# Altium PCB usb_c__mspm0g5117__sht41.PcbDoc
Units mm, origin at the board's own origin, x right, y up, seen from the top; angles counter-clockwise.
Board outline 92 x 60 mm, 2 copper layers (Top, Bottom), stack 0 mm thick; 35 components, 31 nets, 176 pads, 58 vias.
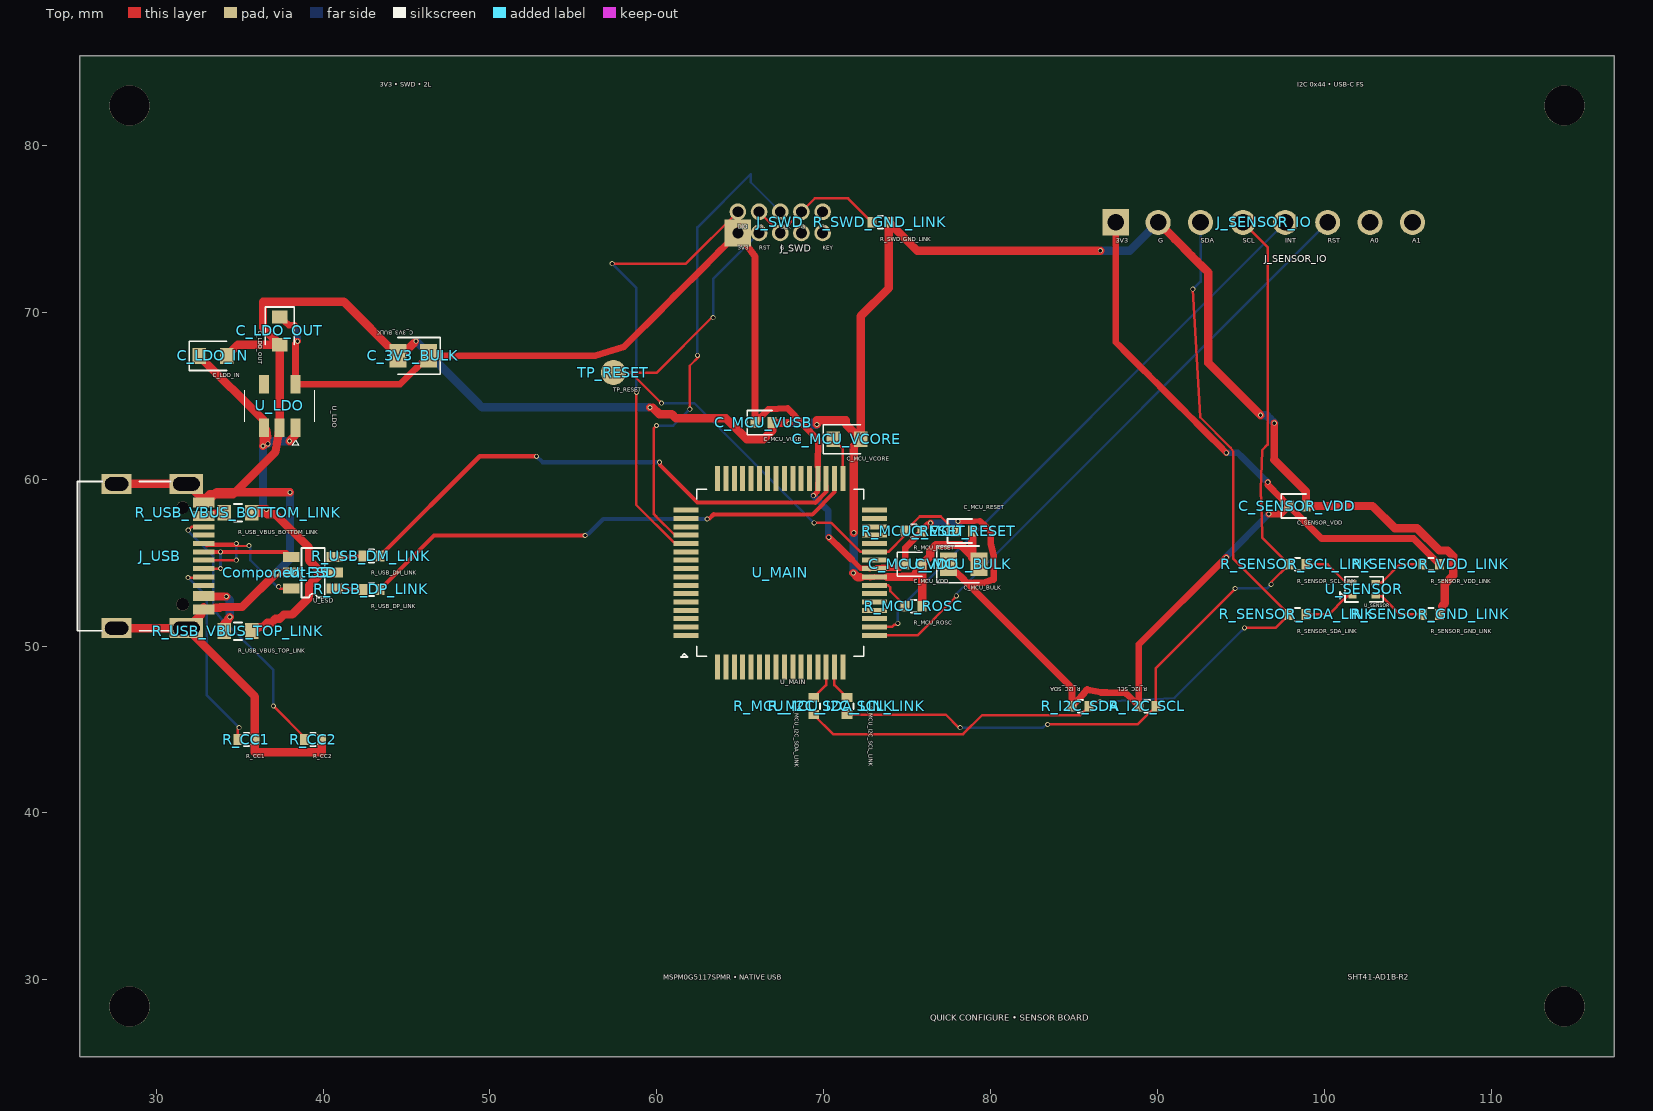
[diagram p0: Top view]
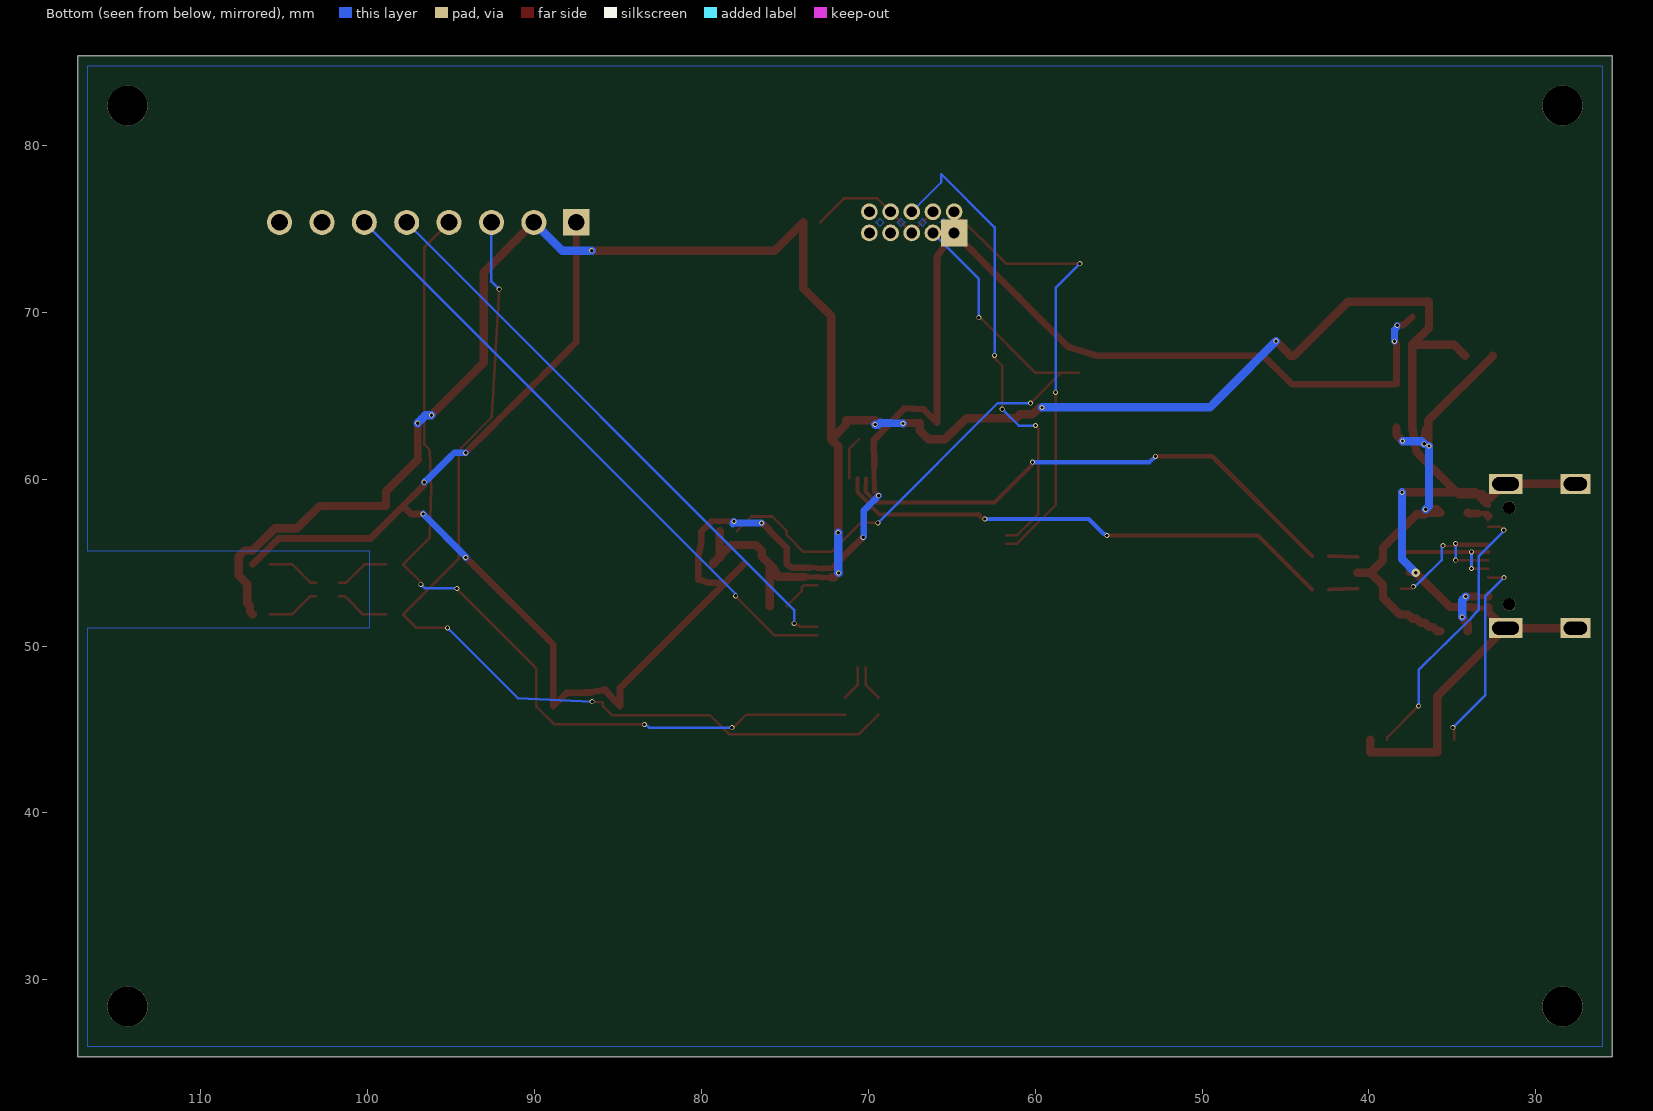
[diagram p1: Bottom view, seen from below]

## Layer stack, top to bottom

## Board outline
25.4,85.4 117.4,85.4 117.4,25.4 25.4,25.4

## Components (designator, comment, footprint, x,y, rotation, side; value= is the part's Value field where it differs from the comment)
C_3V3_BULK "" TSCIRCUIT-2.8500x1.4000mm 45.4,67.4 r180 top
C_LDO_IN "" TSCIRCUIT-2.4500x0.9500mm 33.4,67.4 r0 top
C_LDO_OUT "" TSCIRCUIT-0.9500x2.4500mm 37.4,68.9 r270 top
C_MCU_BULK "" TSCIRCUIT-2.8500x1.4000mm 78.4,54.9 r0 top
C_MCU_RESET "" TSCIRCUIT-1.5600x0.6400mm 78.4,56.9 r0 top
C_MCU_VCORE "" TSCIRCUIT-2.4500x0.9500mm 71.4,62.4 r0 top
C_MCU_VDD "" TSCIRCUIT-1.5600x0.6400mm 75.4,54.9 r0 top
C_MCU_VUSB "" TSCIRCUIT-1.5600x0.6400mm 66.4,63.4 r0 top
C_SENSOR_VDD "" TSCIRCUIT-1.5600x0.6400mm 98.4,58.4 r0 top
Component-35 "" TSCIRCUIT-0.5000x0.5000mm 37.2,54.4 r0 top
J_SENSOR_IO "" TSCIRCUIT-19.2800x1.5000mm 96.4,75.4 r0 top
J_SWD "" TSCIRCUIT-6.0800x2.2700mm 67.4,75.4 r0 top
J_USB "" TSCIRCUIT-6.7732x9.8502mm 30.113,55.4 r90 top
R_CC1 "" TSCIRCUIT-1.5600x0.6400mm 35.4,44.4 r0 top
R_CC2 "" TSCIRCUIT-1.5600x0.6400mm 39.4,44.4 r0 top
R_I2C_SCL "" TSCIRCUIT-1.5600x0.6400mm 89.4,46.4 r180 top
R_I2C_SDA "" TSCIRCUIT-1.5600x0.6400mm 85.4,46.4 r180 top
R_MCU_I2C_SCL_LINK "" TSCIRCUIT-0.6400x1.5600mm 71.4,46.4 r270 top
R_MCU_I2C_SDA_LINK "" TSCIRCUIT-0.6400x1.5600mm 69.4,46.4 r270 top
R_MCU_RESET "" TSCIRCUIT-1.5600x0.6400mm 75.4,56.9 r0 top
R_MCU_ROSC "" TSCIRCUIT-1.5600x0.6400mm 75.4,52.4 r0 top
R_SENSOR_GND_LINK "" TSCIRCUIT-1.5600x0.6400mm 106.4,51.9 r0 top
R_SENSOR_SCL_LINK "" TSCIRCUIT-1.5600x0.6400mm 98.4,54.9 r0 top
R_SENSOR_SDA_LINK "" TSCIRCUIT-1.5600x0.6400mm 98.4,51.9 r0 top
R_SENSOR_VDD_LINK "" TSCIRCUIT-1.5600x0.6400mm 106.4,54.9 r0 top
R_SWD_GND_LINK "" TSCIRCUIT-1.5600x0.6400mm 73.4,75.4 r0 top
R_USB_DM_LINK "" TSCIRCUIT-1.5600x0.6400mm 42.9,55.4 r0 top
R_USB_DP_LINK "" TSCIRCUIT-1.5600x0.6400mm 42.9,53.4 r0 top
R_USB_VBUS_BOTTOM_LINK "" TSCIRCUIT-2.4500x0.9500mm 34.9,58 r0 top
R_USB_VBUS_TOP_LINK "" TSCIRCUIT-2.4500x0.9500mm 34.9,50.9 r0 top
TP_RESET "" TSCIRCUIT-1.5000x1.5000mm 57.4,66.4 r0 top
U_ESD "" TSCIRCUIT-3.6000x2.5000mm 39.4,54.4 r0 top
U_LDO "" TSCIRCUIT-2.5000x3.7000mm 37.4,64.4 r270 top
U_MAIN "" TSCIRCUIT-12.8000x12.8000mm 67.4,54.4 r0 top
U_SENSOR "" TSCIRCUIT-1.9000x1.1001mm 102.4,53.4 r0 top

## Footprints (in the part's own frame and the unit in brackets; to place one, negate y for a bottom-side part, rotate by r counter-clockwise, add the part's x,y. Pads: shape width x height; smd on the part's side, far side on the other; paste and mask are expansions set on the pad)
TSCIRCUIT-0.5000x0.5000mm [mm]
TSCIRCUIT-0.6400x1.5600mm [mm]
  rect 0.54x0.64 smd: 1(-0.51,0) 2(0.51,0)
  silkscreen extent -0.15,-0.38 0.15,0.38
TSCIRCUIT-0.9500x2.4500mm [mm]
  rect 0.8x0.95 smd: 1(-0.825,0) 2(0.825,0)
  silkscreen extent -1.43,-0.87 0.82,0.88
TSCIRCUIT-1.5000x1.5000mm [mm]
  round 1.5 smd: 1(0,0)
TSCIRCUIT-1.5600x0.6400mm [mm]
  rect 0.54x0.64 smd: 1(-0.51,0) 2(0.51,0)
  silkscreen extent -0.98,-0.72 0.51,0.72
TSCIRCUIT-1.9000x1.1001mm [mm]
  rect 0.5x0.3 smd: 1(-0.7,-0.4) 2(-0.7,0.4) 3(0.7,0.4) 4(0.7,-0.4)
  silkscreen extent -1.45,-0.75 1.15,0.75
TSCIRCUIT-2.4500x0.9500mm [mm]
  rect 0.8x0.95 smd: 1(-0.825,0) 2(0.825,0)
  silkscreen extent -1.42,-0.87 0.82,0.87
TSCIRCUIT-2.5000x3.7000mm [mm]
  rect 1.1x0.6 smd: 1(1.3,0.95) 2(1.3,0) 3(1.3,-0.95) 4(-1.3,-0.95) 5(-1.3,0.95)
  silkscreen extent -0.95,-2.1 2.35,2.1
TSCIRCUIT-2.8500x1.4000mm [mm]
  rect 1.025x1.4 smd: 1(-0.913,0) 2(0.913,0)
  silkscreen extent -1.63,-1.1 0.91,1.1
TSCIRCUIT-3.6000x2.5000mm [mm]
  rect 1x0.6 smd: 1(-1.3,-0.95) 2(-1.3,0) 3(-1.3,0.95) 4(1.3,0.95) 5(1.3,0) 6(1.3,-0.95)
  silkscreen extent -0.7,-1.49 0.7,1.49
TSCIRCUIT-6.0800x2.2700mm [mm]
  rect 1.6x1.6 hole 0.65: 1(-2.54,-0.635)
  round 1 hole 0.65: 2(-2.54,0.635) 3(-1.27,0.635) 4(0,0.635) 5(1.27,0.635) 6(2.54,0.635) 7(2.54,-0.635) 8(1.27,-0.635) 9(0,-0.635) 10(-1.27,-0.635)
TSCIRCUIT-6.7732x9.8502mm [mm]
  rect 0.3x1.3 smd: 1(-3.35,-2.737) 2(-3.05,-2.737) 3(-2.55,-2.737) 4(-2.25,-2.737) 5(-1.75,-2.737) 6(-1.25,-2.737) 7(-0.75,-2.737) 8(-0.25,-2.737) 9(0.25,-2.737) 10(0.75,-2.737) 11(1.25,-2.737) 12(1.75,-2.737) 13(2.55,-2.737) 14(2.25,-2.737) 15(3.35,-2.737) 16(3.05,-2.737)
  rect 1.2x2 hole 0.8 slot 1.6 at 90 deg: 17(-4.325,-1.693) 18(4.325,-1.693)
  rect 1.2x1.8 hole 0.8 slot 1.4 at 90 deg: 19(4.325,2.487) 20(-4.325,2.487)
  round 0.75 hole 0.75 unplated: NPTH-1(-2.9,-1.468) NPTH-2(2.9,-1.468)
  silkscreen extent -4.47,-0.75 4.47,4.83
TSCIRCUIT-12.8000x12.8000mm [mm]
  rect 1.5x0.3 smd: 1(-5.65,-3.75) 2(-5.65,-3.25) 3(-5.65,-2.75) 4(-5.65,-2.25) 5(-5.65,-1.75) 6(-5.65,-1.25) 7(-5.65,-0.75) 8(-5.65,-0.25) 9(-5.65,0.25) 10(-5.65,0.75) 11(-5.65,1.25) 12(-5.65,1.75) 13(-5.65,2.25) 14(-5.65,2.75) 15(-5.65,3.25) 16(-5.65,3.75) 33(5.65,3.75) 34(5.65,3.25) 35(5.65,2.75) 36(5.65,2.25) 37(5.65,1.75) 38(5.65,1.25) 39(5.65,0.75) 40(5.65,0.25) 41(5.65,-0.25) 42(5.65,-0.75) 43(5.65,-1.25) 44(5.65,-1.75) 45(5.65,-2.25) 46(5.65,-2.75) 47(5.65,-3.25) 48(5.65,-3.75)
  rect 0.3x1.5 smd: 17(-3.75,5.65) 18(-3.25,5.65) 19(-2.75,5.65) 20(-2.25,5.65) 21(-1.75,5.65) 22(-1.25,5.65) 23(-0.75,5.65) 24(-0.25,5.65) 25(0.25,5.65) 26(0.75,5.65) 27(1.25,5.65) 28(1.75,5.65) 29(2.25,5.65) 30(2.75,5.65) 31(3.25,5.65) 32(3.75,5.65) 49(3.75,-5.65) 50(3.25,-5.65) 51(2.75,-5.65) 52(2.25,-5.65) 53(1.75,-5.65) 54(1.25,-5.65) 55(0.75,-5.65) 56(0.25,-5.65) 57(-0.25,-5.65) 58(-0.75,-5.65) 59(-1.25,-5.65) 60(-1.75,-5.65) 61(-2.25,-5.65) 62(-2.75,-5.65) 63(-3.25,-5.65) 64(-3.75,-5.65)
  silkscreen extent -5.95,-5.05 5,5
TSCIRCUIT-19.2800x1.5000mm [mm]
  rect 1.6x1.6 hole 1: 1(-8.89,0)
  round 1.5 hole 1: 2(-6.35,0) 3(-3.81,0) 4(-1.27,0) 5(1.27,0) 6(3.81,0) 7(6.35,0) 8(8.89,0)

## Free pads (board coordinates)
  round 2.4 hole 2.4 unplated: NPTH-3(28.4,28.4) NPTH-4(114.4,28.4) NPTH-5(28.4,82.4) NPTH-6(114.4,82.4)

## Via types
v1: diameter 0.3, hole 0.2, Top to Bottom, 57 vias
v2: diameter 0.5, hole 0.2, Top to Bottom, 1 vias

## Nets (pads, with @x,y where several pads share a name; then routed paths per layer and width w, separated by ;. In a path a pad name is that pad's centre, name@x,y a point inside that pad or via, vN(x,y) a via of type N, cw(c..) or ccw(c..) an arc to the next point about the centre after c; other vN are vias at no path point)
".J_SWD > .pin2 to .U_MAIN > .pin12": J_SWD.2 U_MAIN.12 | length 27.8
  Top w0.15: v1(57.327,72.925) 61.75,72.925 J_SWD.2 ; v1(58.781,65.209) 58.755,65.183 58.77,65.169 58.77,58.462 61.081,56.15 U_MAIN.12
  Bottom w0.15: v1(57.327,72.925) 57.377,72.875 58.781,71.471 v1(58.781,65.209)
".J_SWD > .pin4 to .U_MAIN > .pin13": J_SWD.4 U_MAIN.13 | length 28.9
  Top w0.15: v1(59.983,63.222) 59.827,63.066 59.821,62.965 59.823,57.912 59.964,57.772 61.084,56.646 U_MAIN.13 ; v1(61.977,64.204) 61.977,66.805 62.526,67.354 62.511,67.354 v1(62.435,67.43)
  Bottom w0.15: v1(59.983,63.222) 60.987,63.222 61.867,64.102 61.874,64.102 v1(61.977,64.204) ; v1(62.435,67.43) 62.435,75.101 65.633,78.299 65.633,77.802 J_SWD.4
".U_MAIN > .pin42 to .R_MCU_ROSC > .pin1": R_MCU_ROSC.1 U_MAIN.42 | length 2.5
  Top w0.15: U_MAIN.42 73.86,53.65 73.994,53.516 73.994,53.296 R_MCU_ROSC.1
GND: C_3V3_BULK.2 C_LDO_IN.2 C_LDO_OUT.2 C_MCU_BULK.2 C_MCU_RESET.2 C_MCU_VCORE.2 C_MCU_VDD.2 C_MCU_VUSB.2 C_SENSOR_VDD.2 J_SENSOR_IO.2 J_USB.1 J_USB.2 J_USB.15 J_USB.16 J_USB.17 J_USB.18 J_USB.19 J_USB.20 R_CC1.2 R_CC2.2 R_MCU_ROSC.2 R_SENSOR_GND_LINK.2 R_SWD_GND_LINK.2 U_ESD.2 U_LDO.2 U_MAIN.41 | length 190.2
  Top w0.3: J_USB.1@32.699,51.9 J_USB.1 J_USB.1@32.849,52.2 ; J_USB.15@32.699,58.9 J_USB.15 ; J_USB.2 33,52.252 33.125,52.296 33.499,52.296 ; J_USB.16 J_USB.16@32.999,58.6 ; J_USB.16@32.849,58.6 J_USB.15 ; J_USB.15@32.999,58.9 J_USB.15 ; 72.3,54.12 72.425,54.12 72.55,54.12 72.675,54.12 U_MAIN.41@72.796,54.111 ; U_MAIN.41 73.144,54.15 73.237,54.15 73.331,54.15 73.425,54.15 73.519,54.15 73.612,54.15 73.706,54.15 U_MAIN.41@73.8,54.15
  Top w0.325: J_USB.16 J_USB.16@32.849,58.6
  Top w0.375: 45.429,68.145 45.435,68.145 v1(45.568,68.278) ; U_MAIN.41@72.796,54.111 U_MAIN.41
  Top w0.4: 37.2,54.4 U_ESD.2@37.6,54.4 ; 72.175,54.12 72.3,54.12
  Top w0.45: 97.017,61.171 97.017,61.61 97.017,62.048 97.017,62.487 97.017,62.926 v1(97.017,63.365)
  Top w0.475: U_MAIN.41@73.8,54.15 74.253,54.15 74.707,54.15
  Top w0.5: J_USB.20 J_USB.17 ; J_USB.19 J_USB.18 31.874,59.725 32.474,59.125 32.699,58.9 ; 32.699,51.9 32.474,51.675 31.874,51.075 J_USB.17 ; J_USB.1@32.849,52.2 J_USB.2 ; J_USB.15@32.999,58.6 33.626,59.227 38.006,59.227 v1(38.016,59.217) ; 32.999,58.9 33.197,59.098 34.598,59.098 37.15,61.65 U_LDO.2 C_LDO_OUT.2 ; 33.499,52.296 33.795,52.296 33.849,52.35 35.15,52.35 37.2,54.4 ; C_LDO_IN.2 34.9,68.075 C_LDO_OUT.2 ; R_CC2.2 39.91,43.65 35.91,43.65 R_CC1.2 35.91,46.971 J_USB.17 ; 45.429,68.145 45.181,67.897 44.932,67.648 44.684,67.4 C_3V3_BULK.2 41.237,70.65 36.4,70.65 36.4,69.075 C_LDO_OUT.2 ; v1(59.596,64.301) 59.749,64.301 60.15,63.9 60.9,63.9 61.15,63.65 64.15,63.65 65.4,62.4 66.4,62.4 66.91,62.91 C_MCU_VUSB.2 67.885,63.375 v1(67.928,63.349) ; v1(69.589,63.289) 69.589,63.539 71.336,63.539 71.336,63.289 C_MCU_VCORE.2 ; v1(71.783,54.383) 72.043,54.113 72.175,54.12 ; v1(71.813,56.799) v1(71.813,56.799) 71.814,56.82 71.814,61.989 C_MCU_VCORE.2 ; 74.707,54.15 75.4,54.15 75.66,54.65 C_MCU_VDD.2 ; R_MCU_ROSC.2 C_MCU_VDD.2 ; C_MCU_RESET.2 78.91,55.303 C_MCU_BULK.2 79.313,54.988 78.233,56.067 76.733,56.067 76.4,55.733 76.4,55.4 75.9,54.9 C_MCU_VDD.2 ; v1(86.586,73.702) 75.608,73.702 R_SWD_GND_LINK.2 73.91,71.464 72.225,69.779 72.225,69.287 72.225,68.795 72.225,68.303 72.225,67.812 72.225,67.32 72.225,66.828 72.225,66.336 72.225,65.844 72.225,65.352 72.225,64.86 72.225,64.368 72.225,63.876 72.225,63.384 72.225,62.892 C_MCU_VCORE.2 ; J_SENSOR_IO.2 90.384,75.066 90.719,74.731 91.053,74.397 91.387,74.063 91.721,73.729 92.056,73.394 92.39,73.06 92.724,72.726 93.058,72.392 93.058,66.971 v1(96.182,63.847) ; 97.017,61.171 98.91,59.278 C_SENSOR_VDD.2 99.406,58.4 99.903,58.4 100.399,58.4 100.896,58.4 101.392,58.4 101.888,58.4 102.385,58.4 102.881,58.4 102.9,58.4 104.233,57.067 105.567,57.067 106.9,55.733 107.4,55.733 107.733,55.4 107.733,54.233 107.233,53.733 107.233,52.567 107.067,52.4 107.067,52.067 106.9,51.9 R_SENSOR_GND_LINK.2
  Bottom w0.5: 37.2,54.4 38.016,55.216 v1(38.016,59.217) ; v1(45.568,68.278) 45.898,67.948 46.228,67.618 46.558,67.288 46.888,66.958 47.218,66.628 47.548,66.298 47.878,65.968 48.208,65.638 48.538,65.308 48.868,64.978 49.198,64.648 49.528,64.318 50.023,64.318 50.518,64.318 51.013,64.318 51.508,64.318 52.003,64.318 52.498,64.318 52.993,64.318 53.488,64.318 53.983,64.318 54.477,64.318 54.972,64.318 55.467,64.318 55.962,64.318 56.457,64.318 56.952,64.318 57.447,64.318 57.942,64.318 58.437,64.318 58.932,64.318 59.426,64.318 59.579,64.318 v1(59.596,64.301) ; v1(67.928,63.349) 69.286,63.4 69.422,63.263 69.563,63.263 v1(69.589,63.289) ; v1(71.783,54.383) 71.813,54.413 v1(71.813,56.799) ; v1(86.586,73.702) 88.352,73.702 J_SENSOR_IO.2 ; v1(96.182,63.847) 96.535,63.847 96.762,63.62 96.99,63.392 v1(97.017,63.365)
MAIN_RESET: C_MCU_RESET.1 J_SWD.10 R_MCU_RESET.1 TP_RESET.1 U_MAIN.38 | length 39.9
  Top w0.15: v1(60.281,64.561) 60.192,64.65 60.189,64.65 58.439,66.4 TP_RESET.1 60.006,66.4 63.29,69.683 63.366,69.683 v1(63.375,69.692) ; v1(69.428,57.392) 70.467,57.392 72.205,55.654 73.046,55.654 U_MAIN.38 73.889,55.65 74.89,56.651 R_MCU_RESET.1@74.89,56.9 ; R_MCU_RESET.1 75.761,57.771 77.019,57.771 C_MCU_RESET.1
  Bottom w0.15: v1(60.281,64.561) 62.25,64.561 69.341,57.47 69.35,57.47 v1(69.428,57.392) ; v1(63.375,69.692) 63.375,72.01 J_SWD.10
MCU_I2C_SCL_LOCAL: R_MCU_I2C_SCL_LINK.1 U_MAIN.50 | length 2.2
  Top w0.15: U_MAIN.50 70.65,47.66 R_MCU_I2C_SCL_LINK.1
MCU_I2C_SDA_LOCAL: R_MCU_I2C_SDA_LINK.1 U_MAIN.51 | length 2.2
  Top w0.15: R_MCU_I2C_SDA_LINK.1 70.15,47.66 U_MAIN.51
MSPM0_VCORE: C_MCU_VCORE.1 U_MAIN.32 | length 2.6
  Top w0.15: C_MCU_VCORE.1 71.15,61.825 U_MAIN.32
SENSOR_ADDR0: J_SENSOR_IO.7
SENSOR_ADDR1: J_SENSOR_IO.8
SENSOR_INT: J_SENSOR_IO.5 U_MAIN.47 | length 35.1
  Top w0.15: U_MAIN.47 74.091,51.15 74.239,51.298 74.378,51.298 v1(74.447,51.367)
  Bottom w0.15: v1(74.447,51.367) 74.447,52.177 J_SENSOR_IO.5
SENSOR_RESET: J_SENSOR_IO.6 U_MAIN.48 | length 37.5
  Top w0.15: U_MAIN.48 75.618,50.65 77.868,52.9 77.868,52.928 v1(77.952,53.012)
  Bottom w0.15: v1(77.952,53.012) 77.952,53.142 J_SENSOR_IO.6
SENSOR_SCL: J_SENSOR_IO.4 R_I2C_SCL.1 R_MCU_I2C_SCL_LINK.2 R_SENSOR_SCL_LINK.1 | length 54.2
  Top w0.15: R_MCU_I2C_SCL_LINK.2 77.333,45.89 78.087,45.136 78.16,45.136 v1(78.181,45.115) ; v1(83.426,45.306) 88.816,45.306 R_I2C_SCL.1 89.91,48.687 94.656,53.434 94.656,53.446 v1(94.668,53.458) ; J_SENSOR_IO.4 96.615,73.915 96.615,62.077 96.278,61.744 96.208,59.389 96.28,56.734 96.283,56.507 R_SENSOR_SCL_LINK.1 96.82,53.83 v1(96.82,53.705)
  Bottom w0.15: v1(78.181,45.115) 83.145,45.115 83.347,45.316 83.416,45.316 v1(83.426,45.306) ; v1(94.668,53.458) 96.573,53.458 96.815,53.7 v1(96.82,53.705)
SENSOR_SDA: J_SENSOR_IO.3 R_I2C_SDA.1 R_MCU_I2C_SDA_LINK.2 R_SENSOR_SDA_LINK.1 | length 57.9
  Top w0.15: R_MCU_I2C_SDA_LINK.2 70.567,44.723 78.36,44.723 79.507,45.87 85.38,45.87 R_I2C_SDA.1 85.91,46.65 v1(86.55,46.675) ; v1(92.13,71.392) 92.574,63.719 94.396,61.89 94.564,61.652 94.564,55.226 R_SENSOR_SDA_LINK.1 97.083,51.093 v1(95.221,51.093)
  Bottom w0.15: v1(86.55,46.675) 91.003,46.875 95.049,50.921 v1(95.221,51.093) ; v1(92.13,71.392) 92.14,71.402 92.59,71.852 J_SENSOR_IO.3
SHT_GND_LOCAL: R_SENSOR_GND_LINK.1 U_SENSOR.4 | length 3.2
  Top w0.15: U_SENSOR.4 103.44,53 103.468,52.974 103.551,52.891 104.542,51.9 R_SENSOR_GND_LINK.1
SHT_SCL_LOCAL: R_SENSOR_SCL_LINK.2 U_SENSOR.2 | length 3.2
  Top w0.15: R_SENSOR_SCL_LINK.2 100.201,54.9 101.232,53.868 101.291,53.81 101.36,53.8 U_SENSOR.2
SHT_SDA_LOCAL: R_SENSOR_SDA_LINK.2 U_SENSOR.1 | length 3.3
  Top w0.15: R_SENSOR_SDA_LINK.2 100.281,51.9 101.256,52.875 101.313,52.933 101.36,53 U_SENSOR.1
SHT_VDD_LOCAL: R_SENSOR_VDD_LINK.1 U_SENSOR.3 | length 3.3
  Top w0.15: U_SENSOR.3 103.44,53.8 103.463,53.838 103.546,53.921 104.525,54.9 R_SENSOR_VDD_LINK.1
swd-ground-1-to-2: J_SWD.3 J_SWD.5 J_SWD.9 R_SWD_GND_LINK.1 | length 8.8
  Top w0.15: J_SWD.3 J_SWD.9 J_SWD.5 69.481,76.846 71.471,76.846 71.471,76.819 R_SWD_GND_LINK.1
usb-dm-device: R_USB_DM_LINK.1 U_ESD.4 | length 1.7
  Top w0.25: U_ESD.4 R_USB_DM_LINK.1
usb-dm-mcu: R_USB_DM_LINK.2 U_MAIN.30 | length 31.5
  Top w0.25: R_USB_DM_LINK.2 49.39,61.38 v1(52.787,61.38) ; v1(60.162,61.027) 60.185,60.994 60.185,60.863 62.437,58.611 69.501,58.593 70.166,59.262 U_MAIN.30
  Bottom w0.25: v1(52.787,61.38) 52.795,61.372 52.797,61.372 53.142,61.027 v1(60.162,61.027)
usb-dm-port-tie: J_USB.7 J_USB.9 U_ESD.3 | length 8.4
  Top w0.15: J_USB.7 v1(33.85,54.65) ; J_USB.9 v1(33.85,55.65)
  Top w0.25: J_USB.9 37.8,55.624 U_ESD.3
  Bottom w0.15: v1(33.85,54.65) v1(33.85,55.65)
usb-dp-device: R_USB_DP_LINK.1 U_ESD.6 | length 1.7
  Top w0.25: U_ESD.6 R_USB_DP_LINK.1
usb-dp-mcu: R_USB_DP_LINK.2 U_MAIN.31 | length 30.5
  Top w0.25: R_USB_DP_LINK.2 46.642,56.632 v1(55.711,56.632) ; v1(63.019,57.62) 63.056,57.657 63.164,57.657 63.411,57.904 69.321,57.894 70.656,59.237 U_MAIN.31
  Bottom w0.25: v1(55.711,56.632) 55.802,56.723 55.892,56.723 56.789,57.62 v1(63.019,57.62)
usb-dp-port-tie: J_USB.8 J_USB.10 U_ESD.1 | length 11.8
  Top w0.15: J_USB.8 v1(34.8,55.15) ; v1(34.8,56.15) J_USB.10 33.021,55.99 v1(35.563,56.026) ; v1(37.337,53.563) 37.311,53.537 37.397,53.45 U_ESD.1
  Bottom w0.15: v1(34.8,55.15) v1(34.8,56.15) ; v1(35.563,56.026) 35.569,55.985 35.631,55.985 35.631,55.158 36.775,54.014 37.226,53.563 v1(37.337,53.563)
USB_CC1: J_USB.6 R_CC1.1 | length 12
  Top w0.15: v1(31.906,54.108) 32.807,54.108 J_USB.6 ; R_CC1.1 34.89,45.023 34.974,45.106 v1(34.968,45.112)
  Bottom w0.15: v1(31.906,54.108) 31.922,54.092 31.922,54.08 33.029,52.973 33.029,52.79 33.029,47.051 v1(34.968,45.112)
USB_CC2: J_USB.12 R_CC2.1 | length 16.5
  Top w0.15: v1(31.917,56.952) 32.115,57.15 J_USB.12 ; v1(37.019,46.41) 37.075,46.354 38.89,44.539 R_CC2.1
  Bottom w0.15: v1(31.917,56.952) 31.988,56.881 31.988,56.823 33.401,55.41 33.401,52.199 33.605,51.995 33.954,51.593 37.019,48.581 v1(37.019,46.41)
USB_VBUS_BOTTOM_LOCAL: J_USB.13 J_USB.14 R_USB_VBUS_BOTTOM_LINK.1 | length 1.6
  Top w0.288: J_USB.13 J_USB.13@32.931,57.928
  Top w0.3: J_USB.14 32.849,57.8 J_USB.13 ; J_USB.13@33.006,57.945 33.083,57.95 33.161,57.95 33.239,57.95 33.317,57.95 33.394,57.95 33.472,57.95 33.499,57.95
  Top w0.35: J_USB.13@32.931,57.928 J_USB.13@33.006,57.945
  Top w0.475: 33.499,57.95 R_USB_VBUS_BOTTOM_LINK.1@33.762,57.95
  Top w0.5: R_USB_VBUS_BOTTOM_LINK.1@33.762,57.95 34.025,57.95 R_USB_VBUS_BOTTOM_LINK.1
USB_VBUS_TOP_LOCAL: J_USB.3 J_USB.4 R_USB_VBUS_TOP_LINK.1 | length 4
  Top w0.3: J_USB.4 32.849,53 J_USB.3 32.975,52.976 33.382,52.976 33.499,52.976
  Top w0.5: 33.499,52.976 33.789,52.976 v1(34.196,52.976) ; R_USB_VBUS_TOP_LINK.1 34.075,51.329 34.302,51.556 34.302,51.638 v1(34.413,51.749)
  Bottom w0.5: v1(34.196,52.976) 34.239,52.933 34.239,52.926 34.413,52.752 34.413,52.418 34.413,52.083 v1(34.413,51.749)
VBUS5: C_LDO_IN.1 R_USB_VBUS_BOTTOM_LINK.2 R_USB_VBUS_TOP_LINK.2 U_ESD.5 U_LDO.1 U_LDO.3 | length 29.2
  Top w0.35: 36.643,62.537 v1(36.687,62.125)
  Top w0.5: C_LDO_IN.1 36.45,63.525 U_LDO.3 ; R_USB_VBUS_TOP_LINK.2 35.9,50.9 36.15,51.15 36.4,51.15 36.65,51.4 36.9,51.4 37.15,51.65 37.4,51.65 37.65,51.9 38.15,51.9 39.15,52.9 39.15,53.65 39.9,54.4 ; v1(36.4,62) 36.45,62.05 U_LDO.3 ; v1(36.6,58.2) 35.925,58.2 R_USB_VBUS_BOTTOM_LINK.2 36.225,58 36.725,58 36.65,57.925 36.65,57.9 37.15,57.9 39.15,55.9 39.15,55.15 39.9,54.4 ; 36.643,62.537 36.6,62.95 U_LDO.3 ; v1(37.987,62.291) 38.35,62.654 U_LDO.1 ; 39.9,54.4 U_ESD.5 39.9,54.4
  Bottom w0.5: v1(36.4,62) 36.4,58.4 v1(36.6,58.2) ; v1(36.687,62.125) 36.853,62.291 v1(37.987,62.291)
VCC_3V3: C_3V3_BULK.1 C_LDO_OUT.1 C_MCU_BULK.1 C_MCU_VDD.1 C_MCU_VUSB.1 C_SENSOR_VDD.1 J_SENSOR_IO.1 J_SWD.1 R_I2C_SCL.2 R_I2C_SDA.2 R_MCU_RESET.2 R_SENSOR_VDD_LINK.2 U_LDO.5 U_MAIN.29 U_MAIN.40 | length 141.3
  Top w0.3: v1(69.378,59.022) 69.494,59.121 69.5,59.128 69.642,59.272 69.646,59.661 U_MAIN.29 69.65,60.15 69.65,60.25 69.65,60.35 69.65,60.45 69.65,60.55 69.65,60.65 69.65,60.75 69.65,60.8 ; 71.668,55.202 71.939,54.938 72.21,54.673 ; U_MAIN.40@72.77,54.658 U_MAIN.40
  Top w0.306: U_MAIN.40 73.162,54.705 U_MAIN.40@73.509,54.704
  Top w0.312: 72.21,54.673 U_MAIN.40@72.49,54.666
  Top w0.325: v1(78.055,57.485) 78.395,57.478 78.714,57.485 79.032,57.493 79.35,57.5
  Top w0.337: 79.35,57.5 79.416,57.457
  Top w0.342: U_MAIN.40@72.49,54.666 U_MAIN.40@72.77,54.658
  Top w0.387: U_MAIN.40@73.509,54.704 73.856,54.703
  Top w0.4: C_LDO_OUT.1 37.96,69.228 v1(38.304,69.229) ; v1(38.469,68.274) 38.399,68.269 38.399,68.18 38.35,68.131 U_LDO.5 44.613,65.7 C_3V3_BULK.1 46.712,67.4 47.111,67.4 47.511,67.4 47.91,67.4 48.309,67.4 48.709,67.4 49.108,67.4 49.508,67.4 49.907,67.4 50.306,67.4 50.706,67.4 51.105,67.4 51.504,67.4 51.904,67.4 52.303,67.4 52.703,67.4 53.102,67.4 53.501,67.4 53.901,67.4 54.3,67.4 54.699,67.4 55.099,67.4 55.498,67.4 55.898,67.4 56.297,67.4 58.041,67.946 58.313,68.218 58.586,68.491 58.859,68.764 59.132,69.037 59.404,69.309 59.677,69.582 59.95,69.855 60.223,70.128 60.496,70.401 60.768,70.673 61.041,70.946 61.314,71.219 61.587,71.492 61.859,71.764 62.132,72.037 62.405,72.31 62.678,72.583 62.951,72.856 63.223,73.128 63.496,73.401 63.769,73.674 64.042,73.947 64.314,74.219 64.587,74.492 J_SWD.1 65.89,73.337 65.89,72.94 65.89,72.542 65.89,72.145 65.89,71.747 65.89,71.35 65.89,70.952 65.89,70.555 65.89,70.158 65.89,69.76 65.89,69.363 65.89,68.965 65.89,68.568 65.89,68.17 65.89,67.773 65.89,67.375 65.89,66.977 65.89,66.58 65.89,66.182 65.89,65.785 65.89,65.387 65.89,64.99 65.89,64.592 65.89,64.195 65.89,63.798 C_MCU_VUSB.1 66.69,64.2 67.84,64.256 69.67,62.353 69.65,60.85 69.65,60.8 ; v1(70.313,56.524) 70.584,56.26 70.855,55.995 71.126,55.731 71.397,55.467 71.668,55.202 ; 73.856,54.703 74.203,54.701 74.55,54.7 C_MCU_VDD.1 74.89,55.88 R_MCU_RESET.2 75.91,56.953 76.068,57.111 76.226,57.269 76.289,57.269 v1(76.401,57.381) ; 79.416,57.457 79.616,57.262 79.815,57.068 80.015,56.873 80.015,56.511 80.015,56.149 80.2,55.4 80.2,54 79.6,53.8 79.515,53.8 79.206,53.8 78.897,53.8 78.588,53.8 78.313,54.075 78.038,54.35 77.763,54.625 C_MCU_BULK.1 84.89,47.498 R_I2C_SDA.2 85.157,46.667 85.8,47.4 86.62,47.226 86.987,47.22 87.355,47.213 87.722,47.207 88.09,47.2 88.357,46.934 88.623,46.667 R_I2C_SCL.2 88.89,50.095 94.056,55.26 94.088,55.26 v1(94.139,55.311) ; J_SENSOR_IO.1 87.51,75.001 87.51,74.602 87.51,74.203 87.51,73.804 87.51,73.405 87.51,73.006 87.51,72.607 87.51,72.208 87.51,71.809 87.51,71.41 87.51,71.011 87.51,70.612 87.51,70.213 87.51,69.814 87.51,69.415 87.51,69.016 87.51,68.617 87.51,68.218 87.784,67.944 88.057,67.671 88.331,67.397 88.604,67.124 88.878,66.85 89.151,66.577 89.425,66.303 89.698,66.03 89.972,65.756 90.246,65.482 90.519,65.209 90.793,64.935 91.066,64.662 91.34,64.388 91.613,64.115 91.887,63.841 92.16,63.568 92.434,63.294 92.708,63.02 92.981,62.747 93.255,62.473 93.528,62.2 93.802,61.926 94.075,61.653 v1(94.14,61.588) ; v1(96.619,59.827) 96.612,59.678 96.868,59.422 97.123,59.167 97.379,58.911 97.634,58.656 C_SENSOR_VDD.1 ; v1(96.682,57.92) 97.41,57.92 C_SENSOR_VDD.1 ; R_SENSOR_VDD_LINK.2 105.361,56.449 105.302,56.449 99.841,56.449 C_SENSOR_VDD.1
  Bottom w0.4: v1(38.304,69.229) 38.348,69.119 38.348,69.077 38.469,68.956 v1(38.469,68.274) ; v1(69.378,59.022) 69.604,58.796 69.83,58.57 70.056,58.344 70.281,58.119 70.281,57.743 70.281,57.368 70.281,56.993 70.281,56.617 70.281,56.556 v1(70.313,56.524) ; v1(76.401,57.381) 76.733,57.381 77.064,57.381 77.396,57.381 77.728,57.381 78.06,57.381 78.124,57.317 78.124,57.388 v1(78.055,57.485) ; v1(94.139,55.311) 94.139,55.377 96.561,57.799 v1(96.682,57.92) ; v1(94.14,61.588) 94.482,61.588 94.824,61.588 95.097,61.315 95.37,61.043 95.642,60.77 95.915,60.497 96.188,60.224 96.461,59.952 96.487,59.952 v1(96.619,59.827)
pads on no net: J_SWD.6 J_SWD.7 J_SWD.8 J_USB.5 J_USB.11 J_USB.NPTH-1 J_USB.NPTH-2 U_LDO.4 U_MAIN.1 U_MAIN.2 U_MAIN.3 U_MAIN.4 U_MAIN.5 U_MAIN.6 U_MAIN.7 U_MAIN.8 U_MAIN.9 U_MAIN.10 U_MAIN.11 U_MAIN.14 U_MAIN.15 U_MAIN.16 U_MAIN.17 U_MAIN.18 U_MAIN.19 U_MAIN.20 U_MAIN.21 U_MAIN.22 U_MAIN.23 U_MAIN.24 U_MAIN.25 U_MAIN.26 U_MAIN.27 U_MAIN.28 U_MAIN.33 U_MAIN.34 U_MAIN.35 U_MAIN.36 U_MAIN.37 U_MAIN.39 U_MAIN.43 U_MAIN.44 U_MAIN.45 U_MAIN.46 U_MAIN.49 U_MAIN.52 U_MAIN.53 U_MAIN.54 U_MAIN.55 U_MAIN.56 U_MAIN.57 U_MAIN.58 U_MAIN.59 U_MAIN.60 U_MAIN.61 U_MAIN.62 U_MAIN.63 U_MAIN.64
copper on no net:
  other v2: 37.2,54.4

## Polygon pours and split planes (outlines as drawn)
GND on Bottom (solid): 116.8,84.8 26,84.8 26,26 116.8,26 116.8,51.1 100.2,51.1 99.9,51.1 99.9,51.4 99.9,55.1 99.9,55.7 100.5,55.7 116.8,55.7
GND on Bottom (solid): 65.495,75.64 65.484,75.618 65.399,75.515 65.591,75.515 65.506,75.618
GND on Bottom (solid): 65.61,75.496 65.61,75.304 65.713,75.389 65.735,75.4 65.713,75.411
GND on Bottom (solid): 69.305,75.64 69.294,75.618 69.2,75.505 69.087,75.411 69.065,75.4 69.087,75.389 69.2,75.295 69.294,75.182 69.305,75.16 69.316,75.182 69.41,75.295 69.523,75.389 69.545,75.4 69.523,75.411 69.41,75.505 69.316,75.618
GND on Bottom (solid): 68.035,75.64 68.024,75.618 67.93,75.505 67.817,75.411 67.795,75.4 67.817,75.389 67.93,75.295 68.024,75.182 68.035,75.16 68.046,75.182 68.14,75.295 68.253,75.389 68.275,75.4 68.253,75.411 68.14,75.505 68.046,75.618
GND on Bottom (solid): 66.765,75.64 66.754,75.618 66.66,75.505 66.547,75.411 66.525,75.4 66.547,75.389 66.66,75.295 66.754,75.182 66.765,75.16 66.776,75.182 66.87,75.295 66.983,75.389 67.005,75.4 66.983,75.411 66.87,75.505 66.776,75.618

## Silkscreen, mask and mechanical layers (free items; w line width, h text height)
Top Overlay:
  text "3V3 • SWD • 2L" at 43.4,83.4 h0.48
  text "I2C 0x44 • USB-C FS" at 98.4,83.4 h0.5
  text "MSPM0G5117SPMR • NATIVE USB" at 60.4,29.9 h0.52
  text "SHT41-AD1B-R2" at 101.4,29.9 h0.55
  text "QUICK CONFIGURE • SENSOR BOARD" at 76.4,27.4 h0.65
